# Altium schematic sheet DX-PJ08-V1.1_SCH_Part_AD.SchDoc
size A4
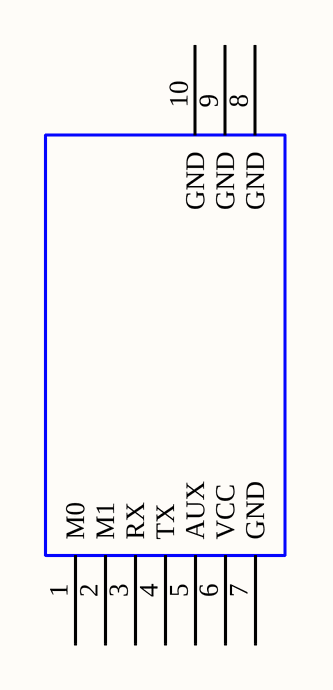
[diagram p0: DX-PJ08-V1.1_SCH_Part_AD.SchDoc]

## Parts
?  (no value)

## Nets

Not connected (* = marked no-connect by the designer): ? 1(M0) 2(M1) 3(RX) 4(TX) 5(AUX) 6(VCC) 7(GND) 8(GND) 9(GND) 10(GND)

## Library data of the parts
? = Component_1_1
